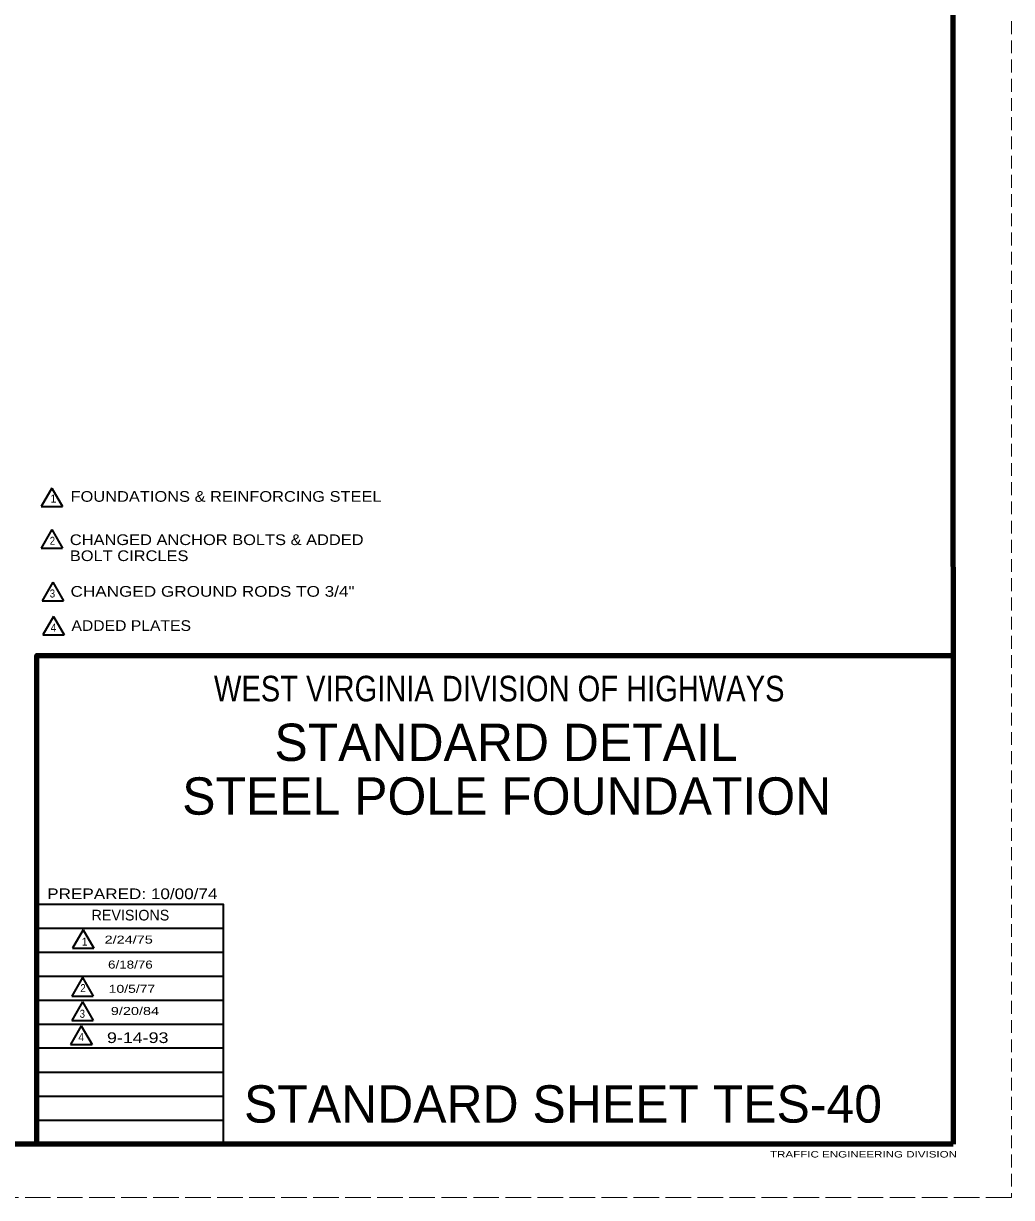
# Model space of a CAD drawing. Extents: x -560 to 120, y 26 to 466.
# Drawn here: x -64.9 to 120.2, y 25.8 to 245.8 of the extents above; entities that cross this region are included whole.
import ezdxf
from ezdxf.enums import TextEntityAlignment as Align

# ---------------------------------------------------------------- set-up
doc = ezdxf.new("R2010")
doc.units = 0
doc.header["$LTSCALE"] = 0.8
doc.linetypes.add('LONG_DASHED', pattern=[7.5, 6, -1.5])
doc.linetypes.add('MEDIUM_DASHED', pattern=[4.5, 3, -1.5])
doc.layers.add('1', color=7, linetype='Continuous', lineweight=53)
doc.layers.add('61', color=7, linetype='Continuous', lineweight=35)

msp = doc.modelspace()

# ---------------------------------------------------------------- linework, layer by layer
at = {"layer": '1', "linetype": 'MEDIUM_DASHED', "lineweight": 13}
msp.add_line((120.2391, 465.8427), (120.2191, 25.8227), dxfattribs=at)
at = {"layer": '1', "lineweight": 35}
for p, q in [((-59.526, 158.7611), (-61.526, 155.297)), ((-59.526, 158.7611), (-57.526, 155.297)), ((-61.526, 155.297), (-57.526, 155.297)), ((-59.526, 150.9676), (-61.526, 147.5035)), ((-59.526, 150.9676), (-57.526, 147.5035)), ((-61.526, 147.5035), (-57.526, 147.5035)), ((-59.3961, 141.0958), (-61.3961, 137.6317)), ((-59.3961, 141.0958), (-57.3961, 137.6317)), ((-61.3961, 137.6317), (-57.3961, 137.6317)), ((-59.2229, 134.6872), (-61.2229, 131.2231)), ((-59.2229, 134.6872), (-57.2229, 131.2231)), ((-61.2229, 131.2231), (-57.2229, 131.2231)), ((-27.3809, 76.2428), (-62.3609, 76.2428)), ((-53.6649, 75.9686), (-55.6649, 72.5045)), ((-53.6649, 75.9686), (-51.6649, 72.5045)), ((-27.3809, 71.7428), (-62.3609, 71.7428)), ((-55.6649, 72.5045), (-51.6649, 72.5045)), ((-27.3809, 67.2428), (-62.3609, 67.2428)), ((-53.7948, 67.0061), (-55.7948, 63.542)), ((-53.7948, 67.0061), (-51.7948, 63.542)), ((-27.3809, 62.7227), (-62.3609, 62.7227)), ((-55.7948, 63.542), (-51.7948, 63.542)), ((-53.7948, 62.4599), (-55.7948, 58.9958)), ((-53.7948, 62.4599), (-51.7948, 58.9958)), ((-27.3809, 58.2428), (-62.3609, 58.2428)), ((-54.0283, 57.9559), (-56.0283, 54.4918)), ((-55.7948, 58.9958), (-51.7948, 58.9958)), ((-54.0283, 57.9559), (-52.0283, 54.4918)), ((-27.3809, 53.7627), (-62.3609, 53.7627)), ((-56.0283, 54.4918), (-52.0283, 54.4918)), ((-27.3809, 49.2627), (-62.3609, 49.2627)), ((-27.3809, 44.7627), (-62.3609, 44.7627)), ((-27.3809, 40.2428), (-62.3609, 40.2428))]:
    msp.add_line(p, q, dxfattribs=at)
at = {"layer": '1', "lineweight": 158}
msp.add_lwpolyline([(-62.3809, 35.8027), (-62.3809, 127.3828), (109.2791, 127.3828)], dxfattribs=at)
at = {"layer": '1', "lineweight": 35}
msp.add_lwpolyline([(-27.3809, 35.7627), (-27.3809, 80.7227), (-62.3609, 80.7227)], dxfattribs=at)
at = {"layer": '61', "lineweight": 158}
for p, q in [((109.2591, 455.8427), (109.2791, 35.8027)), ((109.2791, 35.8027), (-529.7809, 35.8227))]:
    msp.add_line(p, q, dxfattribs=at)
at = {"layer": '61', "linetype": 'LONG_DASHED', "lineweight": 13}
msp.add_line((120.2191, 25.8227), (-559.8409, 25.8027), dxfattribs=at)

# ---------------------------------------------------------------- texts
at = {"layer": '1'}
for s, height, p in [('1', 1.5, (-59.8183, 156.0477)), ('REVISIONS', 1.998, (-52.1009, 77.7227)), ('1', 1.5, (-53.9572, 72.9955)), ('STANDARD SHEET TES-40', 6.993, (-23.5409, 39.8427))]:
    msp.add_text(s, height=height, dxfattribs=at).set_placement(p)
for s, height, width, p in [('FOUNDATIONS & REINFORCING STEEL', 2, 1.15, (-56.0515, 156.1873)), ('2', 1.5, 0.9, (-59.9482, 148.1242)), ('CHANGED ANCHOR BOLTS & ADDED', 2, 1.15, (-56.1814, 148.0754)), ('BOLT CIRCLES', 2, 1.15, (-56.1814, 145.0754)), ('3', 1.5, 0.9, (-59.9483, 138.2525)), ('CHANGED GROUND RODS TO 3/4"', 2, 1.2, (-56.0515, 138.3922)), ('4', 1.5, 0.95, (-59.7752, 131.8438)), ('ADDED PLATES', 2, 1.1, (-55.8783, 131.9836)), ('PREPARED: 10/00/74', 1.998, 1.2, (-60.4209, 81.7227)), ('2/24/75', 1.5, 1.35, (-49.6708, 73.3851)), ('6/18/76', 1.5, 1.25, (-49.0214, 68.709)), ('2', 1.5, 0.9, (-54.2171, 64.2927)), ('10/5/77', 1.5, 1.3, (-48.8915, 64.1628)), ('3', 1.5, 0.9, (-54.3469, 59.4868)), ('9/20/84', 1.5, 1.35, (-48.5018, 60.0063)), ('4', 1.5, 0.95, (-54.5806, 55.1126)), ('TRAFFIC ENGINEERING DIVISION', 1.2, 1.35, (74.9991, 33.3027))]:
    msp.add_text(s, height=height, dxfattribs=dict(at, width=width)).set_placement(p)
for s, height, width, p in [('WEST VIRGINIA DIVISION OF HIGHWAYS', 4.795, 0.85, (24.2674, 118.7827)), ('9-14-93 ', 2, 1.25, (-43.0002, 54.7533))]:
    msp.add_text(s, height=height, dxfattribs=dict(at, width=width)).set_placement(p, align=Align.CENTER)
for s, p in [('STANDARD DETAIL', (25.536, 107.6227)), ('STEEL POLE FOUNDATION', (25.666, 97.5498))]:
    msp.add_text(s, height=6.993, dxfattribs=at).set_placement(p, align=Align.CENTER)

doc.saveas('drawing.dxf')
